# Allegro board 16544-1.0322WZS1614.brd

Outline 236 x 236 mm; copper layers: TOP, L2GND, L3, L4, L5GND, L6, L7GND, BOTTOM. Coordinates in mm from the lower left corner of the outline.
Outline path: 0,235 0,104 arc(0.29,103.29) 1,103 76.7,103 arc(77.41,102.71) 77.7,102 77.7,1 arc(77.99,0.29) 78.7,0 235,0 arc(235.71,0.29) 236,1 236,235 arc(235.71,235.71) 235,236 1,236 arc(0.29,235.71) 0,235 ; 8.75,233.25 9.25,233.25 arc(11.5,231) 9.25,228.75 8.75,228.75 arc(6.5,231) 8.75,233.25 ; 102.4,20.75 arc(103.15,20) 102.4,19.25 arc(101.65,20) 102.4,20.75 ; 109.1,65.95 arc(109.85,65.2) 109.1,64.45 arc(108.35,65.2) 109.1,65.95 ; 228.75,5.25 arc(231,7.5) 233.25,5.25 233.25,4.75 arc(231,2.5) 228.75,4.75 228.75,5.25

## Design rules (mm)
constraint set DEFAULT: min track width 0.127, pair gap 0.102
net group AUDIO_10: nets AUO_3V_POP1 AUO_3V_POP2
net group AUO_HDA_SDIN0_CPU_R: nets AUO_HDA_SDIN0_CPU_R HDA_SDIN0_CPU
net group CPU_USB20_HSD1-DIFF1: nets USB_CPU_PN1 USB_CPU_PP1
net group CPU_USB30_RX1-DIFF1: nets USB30_RX_CPU_N1 USB30_RX_CPU_P1
net group CPU_USB30_TX1-DIFF1: nets USB30_TX_CPU_N1 USB30_TX_CPU_P1
net group DDI0_VGA_DATA_CPU_N0: nets DDI0_VGA_DATA_CPU_N0 DDI0_VGA_DATA_CPU_N0_R
net group DDI0_VGA_DATA_CPU_N1: nets DDI0_VGA_DATA_CPU_N1 DDI0_VGA_DATA_CPU_N1_R
net group DDI0_VGA_DATA_CPU_N2: nets DDI0_VGA_DATA_CPU_N2 DDI0_VGA_DATA_CPU_N2_R
net group DDI0_VGA_DATA_CPU_N3: nets DDI0_VGA_DATA_CPU_N3 DDI0_VGA_DATA_CPU_N3_R
net group DDI0_VGA_DATA_CPU_P0: nets DDI0_VGA_DATA_CPU_P0 DDI0_VGA_DATA_CPU_P0_R
net group DDI0_VGA_DATA_CPU_P1: nets DDI0_VGA_DATA_CPU_P1 DDI0_VGA_DATA_CPU_P1_R
net group DDI0_VGA_DATA_CPU_P2: nets DDI0_VGA_DATA_CPU_P2 DDI0_VGA_DATA_CPU_P2_R
net group DDI0_VGA_DATA_CPU_P3: nets DDI0_VGA_DATA_CPU_P3 DDI0_VGA_DATA_CPU_P3_R
net group DDI1_DATA_CPU_N0: nets DDI1_DATA_CPU_N0 DDI1_DATA_CPU_N0_R
net group DDI1_DATA_CPU_N1: nets DDI1_DATA_CPU_N1 DDI1_DATA_CPU_N1_R
net group DDI1_DATA_CPU_N2: nets DDI1_DATA_CPU_N2 DDI1_DATA_CPU_N2_R
net group DDI1_DATA_CPU_N3: nets DDI1_DATA_CPU_N3 DDI1_DATA_CPU_N3_R
net group DDI1_DATA_CPU_P0: nets DDI1_DATA_CPU_P0 DDI1_DATA_CPU_P0_R
net group DDI1_DATA_CPU_P1: nets DDI1_DATA_CPU_P1 DDI1_DATA_CPU_P1_R
net group DDI1_DATA_CPU_P2: nets DDI1_DATA_CPU_P2 DDI1_DATA_CPU_P2_R
net group DDI1_DATA_CPU_P3: nets DDI1_DATA_CPU_P3 DDI1_DATA_CPU_P3_R
net group DIMM_ADD_CMD_CTL: nets DDR0_A_PARITY DDR1_B_PARITY
net group DMI_RX_CPU_N0: nets DMI_RX_CPU_N0 DMI_RX_CPU_N0_C
net group DMI_RX_CPU_N1: nets DMI_RX_CPU_N1 DMI_RX_CPU_N1_C
net group DMI_RX_CPU_N2: nets DMI_RX_CPU_N2 DMI_RX_CPU_N2_C
net group DMI_RX_CPU_N3: nets DMI_RX_CPU_N3 DMI_RX_CPU_N3_C
net group DMI_RX_CPU_P0: nets DMI_RX_CPU_P0 DMI_RX_CPU_P0_C
net group DMI_RX_CPU_P1: nets DMI_RX_CPU_P1 DMI_RX_CPU_P1_C
net group DMI_RX_CPU_P2: nets DMI_RX_CPU_P2 DMI_RX_CPU_P2_C
net group DMI_RX_CPU_P3: nets DMI_RX_CPU_P3 DMI_RX_CPU_P3_C
net group DMI_TX_CPU_N0: nets DMI_TX_CPU_N0 DMI_TX_CPU_N0_C
net group DMI_TX_CPU_N1: nets DMI_TX_CPU_N1 DMI_TX_CPU_N1_C
net group DMI_TX_CPU_N2: nets DMI_TX_CPU_N2 DMI_TX_CPU_N2_C
net group DMI_TX_CPU_N3: nets DMI_TX_CPU_N3 DMI_TX_CPU_N3_C
net group DMI_TX_CPU_P0: nets DMI_TX_CPU_P0 DMI_TX_CPU_P0_C
net group DMI_TX_CPU_P1: nets DMI_TX_CPU_P1 DMI_TX_CPU_P1_C
net group DMI_TX_CPU_P2: nets DMI_TX_CPU_P2 DMI_TX_CPU_P2_C
net group DMI_TX_CPU_P3: nets DMI_TX_CPU_P3 DMI_TX_CPU_P3_C
net group DP_HPD: nets DDI0_CRT_HPD DDI1_HDMI_HPD
net group GPP_CLK0N: nets GPP_CLK0N GPP_CLK0N_R
net group GPP_CLK0P: nets GPP_CLK0P GPP_CLK0P_R
net group GPU_EDP_AUX_SCL: nets GPU_EDP_AUX_SCL GPU_EDP_AUX_SCL_C
net group GPU_EDP_AUX_SDA: nets GPU_EDP_AUX_SDA GPU_EDP_AUX_SDA_C
net group GPU_EDP_IN0N: nets GPU_EDP_IN0N GPU_EDP_IN0N_C
net group GPU_EDP_IN0P: nets GPU_EDP_IN0P GPU_EDP_IN0P_C
net group GPU_EDP_IN1N: nets GPU_EDP_IN1N GPU_EDP_IN1N_C
net group GPU_EDP_IN1P: nets GPU_EDP_IN1P GPU_EDP_IN1P_C
net group GPU_EDP_IN2N: nets GPU_EDP_IN2N GPU_EDP_IN2N_C
net group GPU_EDP_IN2P: nets GPU_EDP_IN2P GPU_EDP_IN2P_C
net group GPU_EDP_IN3N: nets GPU_EDP_IN3N GPU_EDP_IN3N_C
net group GPU_EDP_IN3P: nets GPU_EDP_IN3P GPU_EDP_IN3P_C
net group GPU_HDMI_OUT0N: nets GPU_HDMI_OUT0N GPU_HDMI_OUT0N_C
net group GPU_HDMI_OUT0P: nets GPU_HDMI_OUT0P GPU_HDMI_OUT0P_C
net group GPU_HDMI_OUT1N: nets GPU_HDMI_OUT1N GPU_HDMI_OUT1N_C
net group GPU_HDMI_OUT1P: nets GPU_HDMI_OUT1P GPU_HDMI_OUT1P_C
net group GPU_HDMI_OUT2N: nets GPU_HDMI_OUT2N GPU_HDMI_OUT2N_C
net group GPU_HDMI_OUT2P: nets GPU_HDMI_OUT2P GPU_HDMI_OUT2P_C
net group GPU_HDMI_OUT_CKN: nets GPU_HDMI_OUT_CKN GPU_HDMI_OUT_CKN_C
net group GPU_HDMI_OUT_CKP: nets GPU_HDMI_OUT_CKP GPU_HDMI_OUT_CKP_C
net group HDA_SDOUT_CODEC: nets HDA_SDOUT_CODEC HDA_SDOUT_CPU
net group HDA_SYNC_CODEC: nets HDA_SYNC_CODEC HDA_SYNC_CPU
net group IPCC_CURRENT_SENSING: nets PWR_CHG_ACN PWR_CHG_ACP
net group PCH_GPP_RX0-DIFF1: nets PCIE_RX_PCH_N0 PCIE_RX_PCH_P0
net group PCH_USB20_HSD2-DIFF1: nets USB_PCH_PN2 USB_PCH_PP2
net group PCH_USB30_RX0-DIFF1: nets USB30_RX_PCH_N0 USB30_RX_PCH_P0
net group PCH_USB30_RX1-DIFF1: nets USB30_RX_PCH_N1 USB30_RX_PCH_P1
net group PCH_USB30_TX0-DIFF1: nets USB30_TX_PCH_N0 USB30_TX_PCH_P0
net group PCH_USB30_TX1-DIFF1: nets USB30_TX_PCH_N1 USB30_TX_PCH_P1
net group PCIE_SSD_RX5-DIFF1: nets PCIE_RX_SSDX4_N5 PCIE_RX_SSDX4_P5
net group PCIE_SSD_RX6-DIFF1: nets PCIE_RX_SSDX4_N6 PCIE_RX_SSDX4_P6
net group PCIE_SSD_RX7-DIFF1: nets PCIE_RX_SSDX4_N7 PCIE_RX_SSDX4_P7
net group PCIE_TX_CON_N0: nets PCIE_TX_CON_N0 PCIE_TX_PCH_N0
net group PCIE_TX_CON_P0: nets PCIE_TX_CON_P0 PCIE_TX_PCH_P0
net group PCIE_TX_LAN_N1: nets PCIE_TX_LAN_N1 PCIE_TX_PCH_N1
net group PCIE_TX_LAN_P1: nets PCIE_TX_LAN_P1 PCIE_TX_PCH_P1
net group PCIE_TX_SSDX4_N4: nets PCIE_TX_SSDX4_N4 PCIE_TX_SSDX4_N4_R
net group PCIE_TX_SSDX4_P4: nets PCIE_TX_SSDX4_P4 PCIE_TX_SSDX4_P4_R
net group PEG_CLK0_WLAN_N: nets PEG_CLK0_WLAN_N PEG_CLK0_WLAN_N_R
net group PEG_CLK0_WLAN_P: nets PEG_CLK0_WLAN_P PEG_CLK0_WLAN_P_R
net group PEG_CLK1_LAN_N: nets PEG_CLK1_LAN_N PEG_CLK1_LAN_N_R
net group PEG_CLK1_LAN_P: nets PEG_CLK1_LAN_P PEG_CLK1_LAN_P_R
net group PEG_CLK4_M2SSD_N: nets PEG_CLK4_M2SSD_N PEG_CLK4_M2SSD_N_R
net group PEG_CLK4_M2SSD_P: nets PEG_CLK4_M2SSD_P PEG_CLK4_M2SSD_P_R
net group PEG_CLK_CPU_N: nets PEG_CLK_CPU_N PEG_CLK_CPU_N_R
net group PEG_CLK_CPU_P: nets PEG_CLK_CPU_P PEG_CLK_CPU_P_R
net group PWR_40_10: nets PWR_0D775V_VIN PWR_12V_SVIN
net group PWR_PWM: nets PWR_VDDNBA_PWM PWR_VDDNBB_PWM
net group SATA_MUXSSD_TX-DIFF1: nets MUXSSD_TX_N1 MUXSSD_TX_P1
net group SATA_RX1-DIFF1: nets SATASSD_RX_DN1 SATASSD_RX_DP1
net group SATA_TX1-DIFF1: nets SATASSD_TX_DN1 SATASSD_TX_DP1
net group USB_CON_PN4: nets USB_CON_PN4 USB_PCH_PN4
net group USB_CON_PP4: nets USB_CON_PP4 USB_PCH_PP4
net group USB_PCH_DN3_NN: nets USB_PCH_DN3_NN USB_PCH_PN3
net group USB_PCH_DP3_PP: nets USB_PCH_DP3_PP USB_PCH_PP3
net group USB_PCH_PN13: nets USB_PCH_PN13 USB_TOUCH_N
net group USB_PCH_PP13: nets USB_PCH_PP13 USB_TOUCH_P
net group AMP_OUT: nets AMP_OUT_D_C WOOF_OUT_A_C1 WOOF_OUT_D_C1
net group AMP_SIGNAL: nets AMP_ASEL AMP_BST_A AMP_BST_B AMP_BST_C AMP_BST_C_C AMP_BST_D AMP_GVDD_AB AMP_GVDD_CD AMP_ISENSEP_L AMP_ISENSEP_R AMP_IVSENSE_L AMP_IVSENSE_R AMP_OC_ADJ AMP_PGVDD AMP_VREF1 AMP_VSENSEN_L AMP_VSENSEN_R GVDD_AB1 OC_ADJ1 PGVDD1 WOOF_ASEL_1 WOOF_BST_A1 WOOF_BST_B1 WOOF_BST_B_C1 WOOF_BST_C1 WOOF_BST_C_C1 WOOF_BST_D1 WOOF_GVDD_CD1 WOOF_ISENSEP_L1 WOOF_ISENSEP_R1 WOOF_IVSENSE_L1 WOOF_IVSENSE_R1 WOOF_VREF2 WOOF_VSENSEN_L1 WOOF_VSENSEN_R1
net group APU_DEBUG: nets APU_DBRDY APU_DBREQ# APU_TCK APU_TDI APU_TDO APU_TMS APU_TRST#
net group APU_FAN: nets CPU_FAN_CTRL_SIO CPU_FAN_TACH_SIO SYS_FAN_TACH1_1 SYS_FAN_TACH1_2 SYSTEM_FAN_PWM1_1
net group AUDIO_15: nets 1D8V_KBC 1D8V_SPI AUO_CBN1 AUO_CBN2 AUO_CBP1 AUO_CBP2 AUO_LDO1_CAP AUO_LDO2_CAP AUO_LDO3_CAP AUO_LINE1-VREF_O_L AUO_LINE1-VREF_O_L_N AUO_LINE1-VREF_O_L_R AUO_LINE1-VREF_O_R_N AUO_LINE1-VREF_O_R_R AUO_MIC1-VREF_O_L AUO_MIC1_CAP AUO_VREF1_1 AUO_VREF_1
net group AUDIO_20: nets AUO_IRQOUT
net group AUDIO_50: nets AUO_VD33STB
net group AUDIO_HPOUT: nets AUO_HPOUT_L AUO_HPOUT_R AUO_MIC1_L AUO_MIC1_R HPOL_CON HPOR_CON HPOUT_L_R HPOUT_R_R
net group AUDIO_I2C: nets AUO_POST_I2S_BCLK AUO_POST_I2S_BCLK_R AUO_POST_I2S_DIN AUO_POST_I2S_DIN_R AUO_POST_I2S_DOUT AUO_POST_I2S_DOUT_R AUO_POST_I2S_LRCK AUO_POST_I2S_LRCK_R
net group AUDIO_LINEOUT: nets AUO_LINE1_L AUO_LINE1_L_T AUO_LINE1_R AUO_LINE1_R_T AUO_LINEOUT_L AUO_LINEOUT_R
net group AUDIO_OTHERS: nets AUO_AGPO_1 AUO_AGPO_1_R AUO_BEEP_C AUO_BEEP_R AUO_CPVEE AUO_CPVPP AUO_EAPD AUO_HP_LINE1_JD AUO_HP_MUTE1 AUO_HP_MUTE2 AUO_HP_MUTE_R AUO_HPOUT_JD AUO_I2S_OUT_MIC1_JD AUO_INL_R2 AUO_INR_L1 AUO_INR_R1 AUO_INR_R2 AUO_LINEOUT_JD AUO_MONITOR_SW AUO_SET1 AUO_SET2 AUO_SIO_HP_MUTE AUO_SPDIF_IN AUO_SPDIF_IN_R PC_MONITOR_SW_D PC_MONITOR_SW_G PDB
net group AUO_LINK_BCLK: nets AUO_LINK_BCLK HDA_BITCLK_CODEC HDA_BITCLK_CPU
net group AUO_RESET_OUT: nets AUO_RESET_OUT HDA_RST#_CODEC HDA_RST#_CPU
net group CHAR_CONTROL: nets CHAR_CTL1_REAR CHAR_CTL1_SIDE CHAR_CTL2_REAR CHAR_CTL2_SIDE CHAR_CTL3_REAR CHAR_CTL3_SIDE PCH_CHAR_CTL3_REAR PCH_CHAR_CTL3_SIDE
net group CHAR_ENABLE: nets CHAR_EN_REAR CHAR_EN_REAR_EC CHAR_EN_SIDE CHAR_EN_SIDE_EC
net group CHAR_OTHERS: nets CHAR_ILIM_HI_REAR CHAR_ILIM_HI_SIDE CHAR_ILIM_LO_REAR CHAR_ILIM_LO_SIDE CHAR_ILIM_SEL_REAR CHAR_ILIM_SEL_SIDE
net group CLK_100M: nets CLK_100M CLK_100M_R XIN_OSC
net group CLKREQ: nets CLK_REQG_L NGFF_CLKREQ1_N PEG_CLKREQ0_NGFF#_C PEG_CLKREQ0_WLAN# PEG_CLKREQ0_WLAN_C PEG_CLKREQ1_LAN# PEG_CLKREQ4_SSD# PEG_CLKREQ5# PEX_CLKREQ_R
net group CPU_VSENSE: nets CPU_CORE_FB_N CPU_CORE_FB_N_R CPU_CORE_FB_P CPU_CORE_FB_P_R CPU_NB_FB_P CPU_NB_FB_P_R
net group DDR_SEQUENCE: nets SE_BJT_B1 SE_BJT_B2 SE_BJT_B3 SE_VDDQ_EN SE_VPP_EN_B
net group DIMM_MISC_A: nets M_A_EVENT# SM_A_DRAMRST# SM_A_DRAMRST#_R
net group DIMM_MISC_B: nets DDR1_B_ALERT_N M_B_EVENT# SM_B_DRAMRST# SM_B_DRAMRST#_R
net group DIMM_SA_SIGNAL: nets SA0_DIMM1 SA0_DIMM2 SA1_DIMM1 SA1_DIMM2 SA2_DIMM1 SA2_DIMM2
net group EC_GPIO: nets AC_OK# EC_BEEP_GPIO_EC EC_CLEAR_RTC EC_PECI EC_SCI# EC_SMI# EC_SWI# ECSCI#_KBC ECSMI#_KBC ECSWI#_KBC GPU_DPLUS KBC_ON#_GATE KBC_ON#_GATE_L KBC_VCORF PSL_IN1# PSL_IN2# PSL_OUT# SDCARD_DET_EC SIO_GREEN_PWM SIO_PME_N SIO_YELLOW SW_ON_N_SIO VD1_EN# VD_IN1 VD_IN2 VD_OUT1# VD_OUT2#
net group EC_SPI_CLK: nets EC_SPI_CLK KBC_SPI_CLK SPI_CLK_CPU
net group EC_SPI_CS0_N: nets EC_SPI_CS0_N KBC_SPI_CS0_N SPI_CS0_N_CPU
net group EC_SPI_SI: nets EC_SPI_SI KBC_SPI_MOSI SPI_SO_CPU_R
net group EC_SPI_SO: nets EC_SPI_SO KBC_SPI_MISO SPI_MISO_CPU
net group GPIO: nets ADAPTOR_PSID ADAPTOR_PSID_R AGPIO89 AUO_DMIC_DET BIST_EN_INV CLEAN_CMOS_EC CMOS_EC_R CORETYPE0 CORETYPE1 CYPD2122_WP DPLVDS_PWMIN DPLVDS_PWMIN_CPU EC_SENSE_BT1 EDP_CABLE_DET EGPIO97 FDT_OVRD_GPIO FDT_OVRD_GPIO_C GPU_BLON_PWM GPU_GPIO_8_ROMSO_R GPU_GPIO_9_ROMSI_R GPU_GPIO_10_ROMSCK GPU_GPIO_10_ROMSCK_R GPU_GPIO_11 GPU_GPIO_12 GPU_GPIO_13 GPU_GPIO_15 GPU_GPIO_19_CTF GPU_GPIO_19_CTF_R GPU_GPIO_20 GPU_GPIO_22_ROMCSB GPU_GPIO_22_ROMCSB_R GPU_GPIO_29 GPU_GPIO_30_PCC_R HDMI_DET HOOD_SW_DET# INT#_TYPEC INT_SERIRQ IPCC_CPU0 IPCC_CPU0_R IPCC_CPU1 IPCC_CPU1_R IPCC_CPU2 IPCC_CPU2_R JACK_PSID LAN_DISABLE_N LPC_PME_N_R LPC_SMI_L M2_PEDET ME_CNTL1 ME_UNLOCK MODEL_ID_DET NC7SB3157_S NGFF_PEWAKE0_N OSD_CONTROL_SEL OSD_MENU OSD_MENU_EC OSD_MENU_R PANEL_ON PB_IN_SW1 PCB_VER_ID PCH_SUSCLK_WLAN PCIE_WAKE# PM_DEBUG_ENABLE PM_GPIO0_X16_PRSNT PM_GPIO1_PCIEX16_DET0 PM_GPIO2_PCIEX16_DET1 PM_GPIO3_PCIEX16_DET2 PM_GPIO4_SSD_DET PM_GPIO_R0 PM_GPIO_R1 PM_GPIO_R2 PM_GPIO_R3 PM_GPIO_R4 PM_GPIO_R5 PM_GPIO_R6 PM_GPIO_R7 PM_GPIO_R8 PM_GPIO_R9 PM_GPIO_R11 PM_GPIO_R12 PM_GPP_INT_PCI_WAKE PM_IFDET0 PM_IFDET1 PM_INT PM_PCIE_WAKE# PM_PKG0 PM_PKG1 PM_PWRBTN_N PM_TESTEN PM_UART_TX PSID_D PSID_D_1 PSID_G PSW_GPIO PWRBTN_N PWRBTN_N_R PWRCN_DET_EC RDISPLAY1_DET_EC RDISPLAY2_DET_EC RLAN_AUDIO_DET_EC RPWR_CN1_DET_EC RTC_DET# RTYPEC_DET_EC RUSB3_DET_EC S5_MUX_APU SMBUS_ISP SPKR SPKR_DET SPKR_DET_C SUSB_DET_EC SUSCLK SUSCLK_NGFF SW_CMOS TOUCH_DET TP_DBGDATA_3_R TP_DBGDATA_4_R TP_DBGDATA_5_R TYPEC_STATUS WEBCAM_DET WOOF_DET_C
net group GPU_ADBIA0_D1: nets ADBIA0 ADBIA1 ADBIB0 ADBIB1 ADBIC0 ADBIC1 ADBID0 ADBID1
net group GPU_CKEA0_D1: nets CKEA0 CKEA1 CKEB0 CKEB1 CKEC0 CKEC1 CKED0 CKED1
net group GPU_CSA0B_CSD1B: nets CSA0B_0 CSA1B_0 CSB0B_0 CSB1B_0 CSC0B_0 CSC1B_0 CSD0B_0 CSD1B_0
net group GPU_DDBIA0: nets DDBIA0_0 DDBIA0_1 DDBIA0_2 DDBIA0_3
net group GPU_DDBIA1: nets DDBIA1_0 DDBIA1_1 DDBIA1_2 DDBIA1_3
net group GPU_DDBIB0: nets DDBIB0_0 DDBIB0_1 DDBIB0_2 DDBIB0_3
net group GPU_DDBIB1: nets DDBIB1_0 DDBIB1_1 DDBIB1_2 DDBIB1_3
net group GPU_DDBIC0: nets DDBIC0_0 DDBIC0_1 DDBIC0_2 DDBIC0_3
net group GPU_DDBIC1: nets DDBIC1_0 DDBIC1_1 DDBIC1_2 DDBIC1_3
net group GPU_DDBID0: nets DDBID0_0 DDBID0_1 DDBID0_2 DDBID0_3
net group GPU_DDBID1: nets DDBID1_0 DDBID1_1 DDBID1_2 DDBID1_3
net group GPU_DQA0_0_31: nets DQA0_0 DQA0_1 DQA0_2 DQA0_3 DQA0_4 DQA0_5 DQA0_6 DQA0_7 DQA0_8 DQA0_9 DQA0_10 DQA0_11 DQA0_12 DQA0_13 DQA0_14 DQA0_15 DQA0_16 DQA0_17 DQA0_18 DQA0_19 DQA0_20 DQA0_21 DQA0_22 DQA0_23 DQA0_24 DQA0_25 DQA0_26 DQA0_27 DQA0_28 DQA0_29 DQA0_30 DQA0_31
net group GPU_DQA1_0_31: nets DQA1_0 DQA1_1 DQA1_2 DQA1_3 DQA1_4 DQA1_5 DQA1_6 DQA1_7 DQA1_8 DQA1_9 DQA1_10 DQA1_11 DQA1_12 DQA1_13 DQA1_14 DQA1_15 DQA1_16 DQA1_17 DQA1_18 DQA1_19 DQA1_20 DQA1_21 DQA1_22 DQA1_23 DQA1_24 DQA1_25 DQA1_26 DQA1_27 DQA1_28 DQA1_29 DQA1_30 DQA1_31
net group GPU_DQB0_0_31: nets DQB0_0 DQB0_1 DQB0_2 DQB0_3 DQB0_4 DQB0_5 DQB0_6 DQB0_7 DQB0_8 DQB0_9 DQB0_10 DQB0_11 DQB0_12 DQB0_13 DQB0_14 DQB0_15 DQB0_16 DQB0_17 DQB0_18 DQB0_19 DQB0_20 DQB0_21 DQB0_22 DQB0_23 DQB0_24 DQB0_25 DQB0_26 DQB0_27 DQB0_28 DQB0_29 DQB0_30 DQB0_31
net group GPU_DQB1_0_31: nets DQB1_0 DQB1_1 DQB1_2 DQB1_3 DQB1_4 DQB1_5 DQB1_6 DQB1_7 DQB1_8 DQB1_9 DQB1_10 DQB1_11 DQB1_12 DQB1_13 DQB1_14 DQB1_15 DQB1_16 DQB1_17 DQB1_18 DQB1_19 DQB1_20 DQB1_21 DQB1_22 DQB1_23 DQB1_24 DQB1_25 DQB1_26 DQB1_27 DQB1_28 DQB1_29 DQB1_30 DQB1_31
net group GPU_DQC0_0_31: nets DQC0_0 DQC0_1 DQC0_2 DQC0_3 DQC0_4 DQC0_5 DQC0_6 DQC0_7 DQC0_8 DQC0_9 DQC0_10 DQC0_11 DQC0_12 DQC0_13 DQC0_14 DQC0_15 DQC0_16 DQC0_17 DQC0_18 DQC0_19 DQC0_20 DQC0_21 DQC0_22 DQC0_23 DQC0_24 DQC0_25 DQC0_26 DQC0_27 DQC0_28 DQC0_29 DQC0_30 DQC0_31
net group GPU_DQC1_0_31: nets DQC1_0 DQC1_1 DQC1_2 DQC1_3 DQC1_4 DQC1_5 DQC1_6 DQC1_7 DQC1_8 DQC1_9 DQC1_10 DQC1_11 DQC1_12 DQC1_13 DQC1_14 DQC1_15 DQC1_16 DQC1_17 DQC1_18 DQC1_19 DQC1_20 DQC1_21 DQC1_22 DQC1_23 DQC1_24 DQC1_25 DQC1_26 DQC1_27 DQC1_28 DQC1_29 DQC1_30 DQC1_31
net group GPU_DQD0_0_31: nets DQD0_0 DQD0_1 DQD0_2 DQD0_3 DQD0_4 DQD0_5 DQD0_6 DQD0_7 DQD0_8 DQD0_9 DQD0_10 DQD0_11 DQD0_12 DQD0_13 DQD0_14 DQD0_15 DQD0_16 DQD0_17 DQD0_18 DQD0_19 DQD0_20 DQD0_21 DQD0_22 DQD0_23 DQD0_24 DQD0_25 DQD0_26 DQD0_27 DQD0_28 DQD0_29 DQD0_30 DQD0_31
net group GPU_DQD1_0_31: nets DQD1_0 DQD1_1 DQD1_2 DQD1_3 DQD1_4 DQD1_5 DQD1_6 DQD1_7 DQD1_8 DQD1_9 DQD1_10 DQD1_11 DQD1_12 DQD1_13 DQD1_14 DQD1_15 DQD1_16 DQD1_17 DQD1_18 DQD1_19 DQD1_20 DQD1_21 DQD1_22 DQD1_23 DQD1_24 DQD1_25 DQD1_26 DQD1_27 DQD1_28 DQD1_29 DQD1_30 DQD1_31
net group GPU_EDCA0_0_3: nets EDCA0_0 EDCA0_1 EDCA0_2 EDCA0_3
net group GPU_EDCA1_0_3: nets EDCA1_0 EDCA1_1 EDCA1_2 EDCA1_3
net group GPU_EDCB0_0_3: nets EDCB0_0 EDCB0_1 EDCB0_2 EDCB0_3
net group GPU_EDCB1_0_3: nets EDCB1_0 EDCB1_1 EDCB1_2 EDCB1_3
net group GPU_EDCC0_0_3: nets EDCC0_0 EDCC0_1 EDCC0_2 EDCC0_3
net group GPU_EDCC1_0_3: nets EDCC1_0 EDCC1_1 EDCC1_2 EDCC1_3
net group GPU_EDCD0_0_3: nets EDCD0_0 EDCD0_1 EDCD0_2 EDCD0_3
net group GPU_EDCD1_0_3: nets EDCD1_0 EDCD1_1 EDCD1_2 EDCD1_3
net group GPU_MAA0_1_8: nets MAA0_0 MAA0_1 MAA0_2 MAA0_3 MAA0_4 MAA0_5 MAA0_6 MAA0_7 MAA0_8
net group GPU_MAA1_1_8: nets MAA1_0 MAA1_1 MAA1_2 MAA1_3 MAA1_4 MAA1_5 MAA1_6 MAA1_7 MAA1_8
net group GPU_MAB0_1_8: nets MAB0_0 MAB0_1 MAB0_2 MAB0_3 MAB0_4 MAB0_5 MAB0_6 MAB0_7 MAB0_8
net group GPU_MAB1_1_8: nets MAB1_0 MAB1_1 MAB1_2 MAB1_3 MAB1_4 MAB1_5 MAB1_6 MAB1_7 MAB1_8
net group GPU_MAC0_1_8: nets MAC0_0 MAC0_1 MAC0_2 MAC0_3 MAC0_4 MAC0_5 MAC0_6 MAC0_7 MAC0_8
net group GPU_MAC1_1_8: nets MAC1_0 MAC1_1 MAC1_2 MAC1_3 MAC1_4 MAC1_5 MAC1_6 MAC1_7 MAC1_8
net group GPU_MAD0_1_8: nets MAD0_0 MAD0_1 MAD0_2 MAD0_3 MAD0_4 MAD0_5 MAD0_6 MAD0_7 MAD0_8
net group GPU_MAD1_1_8: nets MAD1_0 MAD1_1 MAD1_2 MAD1_3 MAD1_4 MAD1_5 MAD1_6 MAD1_7 MAD1_8
net group GPU_MEM_CALR: nets MEM_CALRA MEM_CALRB MEM_CALRC MEM_CALRD
net group GPU_OTHERS: nets CTF_TRIP FB_VDDC_VR FB_VDDCI FB_VSSC GPU_AUX_ZVSS GPU_EDP_HPD GPU_EDP_HPD3 GPU_EDP_HPD4 GPU_GPIO_1 GPU_GPIO_8_ROMSO GPU_GPIO_9_ROMSI GPU_HPD_HDMI GPU_P_ZVSS GPU_PPC_EC GPU_PPC_R GPU_VCC3_CTL GPU_VCC3_CTL_2 GPU_WAKEB HSYNC MF_A0 MF_A1 MF_B0 MF_B1 MF_C0 MF_C1 MF_D0 MF_D1 MVREF_A MVREF_B MVREF_C MVREF_D P2800_DXN P2800_DXP SEN_A0 SEN_A1 SEN_B0 SEN_B1 SEN_C0 SEN_C1 SEN_D0 SEN_D1 SSON# TSS_TEST6 U2506_CLKOUT U2506_INT# VREFC_A0 VREFC_A1 VREFC_B0 VREFC_B1 VREFC_C0 VREFC_C1 VREFC_D0 VREFC_D1 VREFD1_A0 VREFD1_A1 VREFD1_B0 VREFD1_B1 VREFD1_C0 VREFD1_C1 VREFD1_D0 VREFD1_D1 VREFD2_A0 VREFD2_A1 VREFD2_B0 VREFD2_B1 VREFD2_C0 VREFD2_C1 VREFD2_D0 VREFD2_D1 VSYNC ZQ_A0 ZQ_A1 ZQ_B0 ZQ_B1 ZQ_C0 ZQ_C1 ZQ_D0 ZQ_D1
net group GPU_RAS_CAS_WEA_CSA_CKE_A1: nets CASA1B RASA1B WEA1B
net group GPU_RAS_CAS_WEA_CSA_CKEA_A0: nets CASA0B RASA0B WEA0B
net group GPU_RAS_CAS_WEB_CSB_CKE_B0: nets CASB0B RASB0B WEB0B
net group GPU_RAS_CAS_WEB_CSB_CKE_B1: nets CASB1B RASB1B WEB1B
net group GPU_RAS_CAS_WEC_CSC_CKE_C0: nets CASC0B RASC0B WEC0B
net group GPU_RAS_CAS_WEC_CSC_CKE_C1: nets CASC1B RASC1B WEC1B
net group GPU_RAS_CAS_WED_CSD_CKE_D0: nets CASD0B RASD0B WED0B
net group GPU_RAS_CAS_WED_CSD_CKE_D1: nets CASD1B RASD1B WED1B
net group HDT: nets HDT1_11 HDT1_13 HDT1_15 HDT_DBREQ# HDT_TRST#
net group IPCC_OTHERS: nets IPCC_AC_PROTECT IPCC_INT_SIO# IPCC_V_SENSE IPCC_XRES# IPPC_GPU_CMP IPPC_GPU_CMP_R IPPC_GPU_MAN IPPC_GPU_PPC
net group JTAG: nets JTAG_BP_0 JTAG_BP_0_R JTAG_BP_1 JTAG_BP_1_R JTAG_DRAIN JTAG_GATE JTAG_TCK JTAG_TDI JTAG_TDO JTAG_TMS JTAG_TRSTB TESTEN
net group LPC: nets L_AD0 L_AD1 L_AD2 L_AD3 L_FRAME_N
net group MUXSSD_RX_N0: nets MUXSSD_RX_N0_R
net group MUXSSD_RX_P0: nets MUXSSD_RX_P0_R
net group NGFF_OTHERS: nets MPCIE_DISABLE_N NGFF_BT_DISABLE NGFF_PEWAKE1_N NGFF_W_DISABLE1_N NGFF_W_DISABLE2_N
net group PLTRST: nets DRAM_RST1 DRAM_RST1_R DRAM_RST1_RR DRAM_RST2 DRAM_RST2_R DRAM_RST2_RR EC_AUD_RST_N EC_AVCC ECRST# ESPI_RESET_L/KBRST_L PCIE_RST# PCIE_RST#_APU PCIE_RST#_APU_R PLT_RST#_APU PLT_RST#_R PLTRST#_EC_R PLTRST_LAN_N PLTRST_N_1 PLTRST_SSD PM_PCIE_RST RSMRST#_CPU RSMRST_H RSMRST_SIO_N RSMRST_SIO_R RST#_CPU SYS_RESET_L
net group PWR_10_10: nets PWR_0D8V_EN PWR_0D8V_ILMT PWR_0D8V_PG PWR_0D9V_PG PWR_0D775V_EN PWR_0D775V_EN_R PWR_0D775V_VREF PWR_1D05V_EN PWR_1D5V_EN PWR_1D05V_ILMT PWR_1D05V_PG PWR_1D5V_PG PWR_1D8V_EN PWR_1D8V_ILMT PWR_1D8V_PG PWR_1D8V_VCC PWR_1D8V_VGA_EN PWR_1D8V_VGA_PG PWR_1D35V_CS PWR_1D35V_EN PWR_1D35V_PG PWR_1D35V_TON PWR_1D35V_VTTREF PWR_2D5V_EN PWR_2D5V_PCH_EN PWR_2D5V_PCH_PG PWR_2D5V_PG PWR_3D3V_5V_PG PWR_3D3V_CS2 PWR_3D3V_EN2 PWR_3D3V_LDO3 PWR_5V_CS1 PWR_5V_EN1 PWR_5V_LDO5 PWR_12V_EN PWR_12V_PG PWR_12V_SS PWR_12V_VCC PWR_VCCDDC_SENSE_A PWR_VCCDDC_SENSE_B PWR_VCCDDCI_SENSE_A PWR_VCCDDCI_SENSE_B PWR_VCORE_COMP PWR_VCORE_EN PWR_VCORE_IMON PWR_VCORE_ISEN1 PWR_VCORE_ISEN2 PWR_VCORE_ISEN3 PWR_VCORE_ISUMN PWR_VCORE_ISUMN_A PWR_VCORE_PG PWR_VCORE_RTN PWR_VCORE_SVC PWR_VCORE_SVD PWR_VCORE_SVT PWR_VCORE_VRHOT PWR_VCORE_VSEB PWR_VCORE_VSUM_P PWR_VDDC_ADDRESS PWR_VDDC_CONFIG PWR_VDDC_EN PWR_VDDC_PALERT# PWR_VDDC_PCLK PWR_VDDC_PDATA PWR_VDDC_PG PWR_VDDC_PG_A PWR_VDDC_SALERT# PWR_VDDC_SCLK PWR_VDDC_SDATA PWR_VDDC_TEMP PWR_VDDC_THWN PWR_VDDC_VCCS PWR_VDDC_VDDIO PWR_VDDC_VRHOT PWR_VDDCA_EN_A PWR_VDDCA_ISEN_P_A PWR_VDDCA_SMOD# PWR_VDDCA_THWN# PWR_VDDCB_EN_A PWR_VDDCB_ISEN_P_A PWR_VDDCB_SMOD# PWR_VDDCB_THWN# PWR_VDDCC_EN_A PWR_VDDCC_ISEN_P_A PWR_VDDCC_SMOD# PWR_VDDCC_THWN# PWR_VDDCD_EN_A PWR_VDDCD_ISEN_N_A PWR_VDDCD_ISEN_P_A PWR_VDDCD_SMOD# PWR_VDDCD_THWN# PWR_VDDCE_EN_A PWR_VDDCE_ISEN_N_A PWR_VDDCE_ISEN_P_A PWR_VDDCE_SMOD# PWR_VDDCE_THWN# PWR_VDDCF_EN_A PWR_VDDCF_ISEN_N_A PWR_VDDCF_ISEN_P_A PWR_VDDCF_SMOD# PWR_VDDCF_THWN# PWR_VDDCI_EN PWR_VDDCI_EN_A PWR_VDDCI_ISEN_P_A PWR_VDDCI_PG PWR_VDDCI_PG_A PWR_VDDCI_SMOD# PWR_VDDCI_TEMP PWR_VDDCI_THWN PWR_VDDCI_THWN# PWR_VDDNB_COMP PWR_VDDNB_FCCM PWR_VDDNB_IMON PWR_VDDNB_ISEN1 PWR_VDDNB_ISEN2 PWR_VDDNB_ISUMN PWR_VDDNB_ISUMN_A PWR_VDDNB_VSEN PWR_VDDNB_VSUMP PWR_VDDP_EN PWR_VDDP_PFM PWR_VDDP_PG PWR_VDDP_SS PWR_VDDP_TON PWR_VDDQ_CS PWR_VDDQ_EN PWR_VDDQ_EN_R PWR_VDDQ_PG PWR_VDDQ_TON PWR_VDDQ_VTTREF PWR_VGA_PG PWR_VR_PG PWR_VSSDDC_SENSE_A PWR_VSSDDCI_SENSE_A PWR_VTT_EN PWR_VTT_EN_R
net group PWR_20_10: nets PWR_1D05V_VCC PWR_1D35V_VDD PWR_1D35V_VID PWR_VCORE_VDDIO PWR_VDDC_VCC PWR_VDDC_VINSEN PWR_VDDQ_VDD PWR_VDDQ_VID
net group PWR_20_20: nets PWR_0D8V_BOOT PWR_0D8V_BOOT_A PWR_0D8V_FB PWR_0D9V_FB PWR_1D05V_BOOT PWR_1D05V_BOOT_A PWR_1D05V_FB PWR_1D5V_FB PWR_1D05V_FB_A PWR_1D8V_BOOT PWR_1D8V_BOOT_A PWR_1D8V_FB PWR_1D8V_FB_A PWR_1D8V_VGA_FB PWR_1D35V_BOOT PWR_1D35V_BOOT_A PWR_1D35V_FB PWR_1D35V_SNUB PWR_2D5V_FB PWR_3D3V_BOOT2 PWR_3D3V_BOOT2_A PWR_3D3V_FB2 PWR_3D3V_FB2_A PWR_3D3V_SNUB PWR_5V_BOOT1 PWR_5V_BOOT1_A PWR_5V_BYP1 PWR_5V_FB1 PWR_5V_FB1_A PWR_5V_SNUB PWR_12V_BOOT_A PWR_12V_FB_A PWR_12V_SNB PWR_VCORE_FB PWR_VCORE_FB2 PWR_VCORE_FB_A PWR_VCORE_FB_B PWR_VCORE_FB_C PWR_VCOREA_BOOT PWR_VCOREA_BOOT_A PWR_VCOREA_SNB PWR_VCOREB_BOOT_A PWR_VCOREB_SNB PWR_VCOREC_BOOT_A PWR_VCOREC_SNB PWR_VDDCA_BOOT PWR_VDDCA_BOOT_A PWR_VDDCA_SNB PWR_VDDCB_BOOT PWR_VDDCB_BOOT_A PWR_VDDCB_SNB PWR_VDDCC_BOOT PWR_VDDCC_BOOT_A PWR_VDDCC_SNB PWR_VDDCD_BOOT PWR_VDDCD_BOOT_A PWR_VDDCD_SNB PWR_VDDCE_BOOT PWR_VDDCE_BOOT_A PWR_VDDCE_SNB PWR_VDDCF_BOOT PWR_VDDCF_BOOT_A PWR_VDDCF_SNB PWR_VDDCI_BOOT PWR_VDDCI_BOOT_A PWR_VDDCI_SNB PWR_VDDNB_FB PWR_VDDNB_FB_A PWR_VDDNB_FB_B PWR_VDDNB_FB_C PWR_VDDNBA_BOOT PWR_VDDNBA_BOOT_A PWR_VDDNBA_VCC PWR_VDDNBB_BOOT PWR_VDDNBB_BOOT_A PWR_VDDNBB_SNB PWR_VDDP_BT PWR_VDDP_FB PWR_VDDP_FB_A PWR_VDDP_FB_B PWR_VDDP_FB_C PWR_VDDQ_BOOT PWR_VDDQ_BOOT_A PWR_VDDQ_FB PWR_VDDQ_SNUB VDDNB_SN1
net group PWR_60_10: nets GPU_VBIOS_PWR PWR_1D35V_VDDQ PWR_VDDQ_VDDQ
net group PWR_EE_10: nets 1D05V_PCH_S0_CT1 5V_S0_CT1 AD+_2 AMP_LDO_1D5 EC_AD0 EC_VSBY IPCC_CMP_VREF IPCC_VCCD IPCC_VREF WOOF_LDO_1D5_1
net group PWR_EE_20: nets 1D5V_DVDD_IO_S5 1D8V_S0_CT2 3D3V_DVDD_MIC 3D3V_MUX_S0 3D3V_PCH_S0 3D3V_S0_CT2 5V_CODEC_DIGITAL_S0 +TSVDD CLK_100M_VDD EFUSE_PWR VDDIO_AUDIO
net group PWR_EE_30: nets EC_VBKUP V_3P0_BAT_VREG VBAT1 VBAT1_R
net group PWR_EE_40: nets 3D3V_AUX_S5 3D3V_VDD_S0 EC_3D3V_S0 EC_VCC1D8V_S5 EC_VDD3D3 G2042_VDDCR_C IPCC_3D3V_S5 KBC_VCC
net group PWR_EE_100: nets EC_AGND
net group PWR_GATE_SNUBBER_BOOT_PHASE: nets PWR_1D35V_HG PWR_1D35V_LG PWR_3D3V_HG2 PWR_3D3V_LG2 PWR_VDDNBA_HG PWR_VDDNBB_LG PWR_VDDQ_HG
net group PWR_GPU_PWM: nets PWR_VDDCA_PWM PWR_VDDCA_PWM_A PWR_VDDCB_PWM PWR_VDDCB_PWM_A PWR_VDDCC_PWM PWR_VDDCC_PWM_A PWR_VDDCD_PWM PWR_VDDCD_PWM_A PWR_VDDCE_PWM PWR_VDDCE_PWM_A PWR_VDDCF_PWM PWR_VDDCF_PWM_A PWR_VDDCI_PWM PWR_VDDCI_PWM_A
net group PWRGD_EN: nets 0D8V_PG 1D05V_PCH_S0_EN 1D05V_PCH_S5_PG 1D05V_PCH_S5_PG_EC 1D05V_S0_EN 1D5V_S5_PG 1D05V_S5_PWRGD 1D8V_S0_EN 1D8V_S5_PG 1D8V_SPI_EN 1D8V_SPI_EN2 1D8V_SPI_EN3 1D8V_VGA_PG 2D5V_EN 2D5V_PCH_S0_PG 2D5V_S5_PG 3V_5V_POK 5V_3D3V_S0_EN 12V_PG ALERT#_CPU ALL_PWRGD_2 ALL_SYS_PWRGD ALL_SYS_PWRGD_C ALL_SYS_PWRGD_EC GPIO_6_TACH GPU_TEST_PG GPU_TEST_PG_B GPU_TEST_PG_BACO GPU_TEST_PG_BACO_B H_PROCHOT_N H_PROCHOT_N_EC HDT_PWR_EN1 HDT_PWR_EN2 HDT_PWR_EN3 MAINPOWER_CONTROL NC7SB3157_A NPMALERT NSVALERT NVRHOT PGOOD_NB PM_PWGD PURE_HW_SHUTDOWN# PURE_HW_SHUTDOWN#_R PWR_5V3V_EMN_R PWRGD_3V_N PX_EN PX_EN_G PX_ENB S5_ENABLE SE_VPP_EN SIO_EUP_EN# SUS_CLK_CPU_EN SVID_PWRGD T_CRIT# THERM_SYS_SHDN# THERMTRIP_L_CPU THERMTRIP_L_CPU_EC USB_EN_S3WAKE USBVCC31_EN USBVCC32_EN USBVCCTP_EN USBVCCTP_EN_R VCORE_MEM_TEST_PG VCORE_MEM_TEST_PG_BACO VDDP_S5_PG VDDP_S5_PG_EC
net group SATAHDR_RX_DN0: nets SATA__RXN0_C SATA_RXN0_C_N SATAHDR_RX_DN0
net group SATAHDR_RX_DP0: nets SATA__RXP0_C SATA_RXP0_C_N SATAHDR_RX_DP0
net group SATAHDR_TX_DN0: nets SATA__TXN0_C SATA_TXN0_C_N SATAHDR_TX_DN0
net group SATAHDR_TX_DP0: nets SATA__TXP0_C SATA_TXP0_C_N SATAHDR_TX_DP0
net group SINGAL_PD: nets DP_AUX_ZVSS DP_ZVSS FWH_ID0 GPU_DP_ZVSS MA_ZVSS MB_ZVSS P_ZVSS PM_UREXT PREXT STRAP_LPC_CLK_CPU_P0 TEST0_APU TEST1_APU TEST2_APU TEST18_APU TEST19_APU
net group SINGAL_PH: nets AGPIO5_DEVSLP0 ALERT# AM4R1 CLK_REQ0 CLK_REQ1 CLK_REQ2 DP_STEREOSYNC_APU GPU_DP_ZVDD_08 INIT_3V MA_ZV MB_ZV NC7SB3157_B0 NC7SB3157_B1 P_ZVDDP SATA_ZVDDP SIO_SMCLK0 SIO_SMDAT0 STRAP_LPC_CLK_CPU_P1 USB_GPIO_C12 USB_GPIO_C13 VDDQ_BLEED_R1 VDDQ_BLEED_R2
net group SINGLE_ENDED_CLOCK: nets CLK_100M_XIN CLK_100M_XOUT LPC_CLK0 LPC_CLK1 LPC_CLK_D PM_XTAL_25M_IN PM_XTAL_25M_IN_R PM_XTAL_25M_OUT PM_XTAL_25M_OUT_R PROCHOT#_CPU_Q SUS_CLK_CPU_PWR X32K_RTC XTL_32K_XI_RTC XTL_32K_XO_RTC
net group SLP_S3_S5: nets SLP_S3_N_EC SLP_S5_N SLP_S5_N_EC
net group SMBUS: nets AMDTSI_CLK_CPU AMDTSI_DATA_CPU AMP_I2C_SCL AMP_I2C_SDA AUO_DMIC_CLK1 AUO_DMIC_CLK1_R AUO_DMIC_CLK2 AUO_DMIC_CLK2_R AUO_DMIC_DATA1 AUO_DMIC_DATA1_R AUO_DMIC_DATA2 AUO_DMIC_DATA2_R DDCVGACLK DDCVGADAT EC_I2C_CLK EC_I2C_DATA GPU_I2C_SCL GPU_I2C_SDA GPU_SMB_CLK_MAIN GPU_SMB_CLK_MAIN_G GPU_SMB_DATA_MAIN GPU_SMB_DATA_MAIN_G I2C3_CLK_RESUME I2C3_DATA_RESUME I2C_CLK I2C_CLK_CN I2C_DATA I2C_DATA_CN IPCC_I2C_CLK IPCC_I2C_CLK_R IPCC_I2C_DATA IPCC_I2C_DATA_R IPCC_SWD_CLK IPCC_SWD_DATA NCT_CLK NCT_DATA PMSCL PMSDA SMB_CLK_MAIN SMB_DATA_MAIN SML1_CLK_SIO SML1_DATA_SIO SVCLK SVDATA SVID_CLK SVID_DATA TYPE_C_CLK TYPE_C_DATA WOOF_I2C_SCL1 WOOF_I2C_SDA1
net group SPI: nets KBC_SPI_IO2 KBC_SPI_IO3 PM_SPI_SCK PM_SPI_SDI PM_SPI_SDO SPI_CS2_CPU
net group SPI_IO2: nets SPI_IO2_CPU
net group SPI_IO3: nets SPI_IO3_CPU
net group SSD_OTHERS: nets DEVSLP DEVSLP_N DEVSLP_N_GATE MUXSSD_OE# MUXSSD_SEL MUXSSD_SEL_EN MUXSSD_SEL_EN_C PEDET_B SSD_DEVSLP_N SSD_PM_PCIE_WAKE# TP_BBR#
net group TP: nets EC_DEBUG PM_TCK PM_TDI PM_TDO PM_TMS PM_UART_RX PPON_0 PPON_1 PPON_2 PPON_3 PPON_4 PPON_5 PPON_6 PPON_7 PPON_8 PPON_9 PPON_10 PPON_11 PPON_12 PPON_13 TEST46 TP_ANALOGIO TP_CHAR_STATUS_REAR TP_CHAR_STATUS_SIDE TP_CLINK_CLK_LAN TP_CLINK_DATA_LAN TP_CLINK_RST_LAN_N TP_DBGDATA_0 TP_DBGDATA_1 TP_DBGDATA_2 TP_DBGDATA_3 TP_DBGDATA_4 TP_DBGDATA_5 TP_DBGDATA_6 TP_DBGDATA_7 TP_DBGDATA_8 TP_DBGDATA_9 TP_DBGDATA_10 TP_DBGDATA_11 TP_DBGDATA_12 TP_DBGDATA_13 TP_DBGDATA_14 TP_DBGDATA_15 TP_DP_AUXN TP_DP_AUXP TP_DP_HPD TP_DP_ML0N TP_DP_ML0P TP_DP_ML1N TP_DP_ML1P TP_DP_ML2N TP_DP_ML2P TP_DP_ML3N TP_DP_ML3P TP_ESPI_ALERT_L TP_GPU_GPIO_0 TP_GPU_GPIO_2 TP_GPU_GPIO_16 TP_LPC_PD TP_NGFF_COEX1 TP_NGFF_COEX2 TP_NGFF_COEX3 TP_NGFF_LED1 TP_NGFF_LED2 TP_NGFF_MLDIR TP_NGFF_PCIE1_RXN TP_NGFF_PCIE1_RXP TP_NGFF_PCIE1_TXN TP_NGFF_PCIE1_TXP TP_NGFF_REFCLKN1 TP_NGFF_REFCLKP1 TP_PLLCHARZ_H TP_PLLCHARZ_L TP_SMB_CLK_MINI TP_SMB_DATA_MINI TP_TEST15 TP_TEST31 TP_TEST40 TP_TEST41 TP_TEST47 TP_TS_A
net group USB_OC: nets CHAR_USBOC4# CHAR_USBOC6# SLP_S3_N USB20_OC_CR1# USB_OC0N USB_OC1N USB_OC2N USB_OC3N USB_OC4N USB_OC5N USB_OC6N USB_OC7N USBVCCTP_OC

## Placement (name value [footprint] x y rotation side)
BT1  BAT-AAA-BAT-034-P06-A-GP-U  [AAA-BAT-034-P06-A-U]  171.04 18.77 0 top
C1  SCD22U10V2KX-2-GP  [C402H22]  135.57 166.28 270 top
C2  SCD22U10V2KX-2-GP  [C402H22]  135.56 165.4 270 top
C3  SCD22U10V2KX-2-GP  [C402H22]  134.17 176.66 0 top
C4  SCD22U10V2KX-2-GP  [C402H22]  133.28 176.66 0 top
C5  SCD22U10V2KX-2-GP  [C402H22]  135.14 176.66 0 top
C6  SCD22U10V2KX-2-GP  [C402H22]  136 176.66 0 top
C7  SCD22U10V2KX-2-GP  [C402H22]  133.66 170.32 270 top
C8  SCD22U10V2KX-2-GP  [C402H22]  133.66 169.46 270 top
C17  SC15P50V2JN-DL-GP  [C402H22]  142.54 169.06 180 top
C18  SC15P50V2JN-DL-GP  [C402H22]  142.54 171.02 0 top
C21  SC150P50V2JN-3DLGP  [C402H22]  136.6 149.45 0 bottom
C22  SC1P50V2CN-3-GP  [C402H22]  141.31 175.53 0 top
C23  SC1P50V2CN-3-GP  [C402H22]  141.32 177.45 180 top
C24  SCD22U10V2KX-2-GP  [C402H22]  164.15 166.44 270 bottom
C25  SCD22U10V2KX-2-GP  [C402H22]  164.15 165.55 270 bottom
C26  SCD22U10V2KX-2-GP  [C402H22]  166.62 177.8 0 bottom
C27  SCD22U10V2KX-2-GP  [C402H22]  157.99 173.74 270 bottom
C28  SCD22U10V2KX-2-GP  [C402H22]  149.99 177.65 90 bottom
C29  SCD22U10V2KX-2-GP  [C402H22]  170.48 173.89 180 bottom
C30  SCD22U10V2KX-2-GP  [C402H22]  170.43 169.88 270 bottom
C31  SCD22U10V2KX-2-GP  [C402H22]  165.4 158.03 180 bottom
C32  SCD22U10V2KX-2-GP  [C402H22]  170.43 177.8 180 bottom
C33  SCD22U10V2KX-2-GP  [C402H22]  168.53 180.85 180 bottom
C34  SCD22U10V2KX-2-GP  [C402H22]  166.54 175.27 180 bottom
C35  SCD22U10V2KX-2-GP  [C402H22]  163.7 160.16 180 bottom
C36  SC180P50V2JN-1DLGP  [C402H22]  154.05 167.39 270 bottom
C37  SC180P50V2JN-1DLGP  [C402H22]  166.75 181.99 0 bottom
C38  SC4D7U6D3V2MX-1-GP  [C402H22]  164.44 175.4 180 bottom
C39  SC4D7U6D3V2MX-1-GP  [C402H22]  163.43 168.14 0 bottom
C40  SC4D7U6D3V2MX-1-GP  [C402H22]  163.7 164.08 180 bottom
C41  SC4D7U6D3V2MX-1-GP  [C402H22]  163.68 162.17 0 bottom
C42  SC4D7U6D3V2MX-1-GP  [C402H22]  162.81 179.45 270 bottom
C43  SC4D7U6D3V2MX-1-GP  [C402H22]  164.56 172.48 0 bottom
C44  SC4D7U6D3V2MX-1-GP  [C402H22]  162.8 181.23 270 bottom
C45  SC4D7U6D3V2MX-1-GP  [C402H22]  165.1 182.63 0 bottom
C46  SC4D7U6D3V2MX-1-GP  [C402H22]  166.62 179.71 180 bottom
C47  SC4D7U6D3V2MX-1-GP  [C402H22]  163.5 158.11 0 bottom
C48  SC4D7U6D3V2MX-1-GP  [C402H22]  155.57 169.93 180 bottom
C49  SC4D7U6D3V2MX-1-GP  [C402H22]  157.24 171.66 90 bottom
C50  SC4D7U6D3V2MX-1-GP  [C402H22]  159.38 179.45 180 bottom
C51  SC4D7U6D3V2MX-1-GP  [C402H22]  152.27 172.85 0 bottom
C52  SC4D7U6D3V2MX-1-GP  [C402H22]  170.48 171.98 180 bottom
C53  SC4D7U6D3V2MX-1-GP  [C402H22]  157.61 170.18 180 bottom
C54  SC4D7U6D3V2MX-1-GP  [C402H22]  162.81 180.34 270 bottom
C55  SC4D7U6D3V2MX-1-GP  [C402H22]  162.56 175.01 0 bottom
C56  SC4D7U6D3V2MX-1-GP  [C402H22]  155.28 181.79 90 bottom
C57  SC4D7U6D3V2MX-1-GP  [C402H22]  155.07 173.35 90 bottom
C58  SCD22U10V2KX-2-GP  [C402H22]  181.29 166.57 90 bottom
C59  SCD22U10V2KX-2-GP  [C402H22]  180.14 163.4 270 bottom
C60  SCD22U10V2KX-2-GP  [C402H22]  183.21 166.57 270 bottom
C61  SCD22U10V2KX-2-GP  [C402H22]  178.21 166.7 270 bottom
C62  SCD22U10V2KX-2-GP  [C402H22]  176.43 173.83 180 bottom
C63  SCD22U10V2KX-2-GP  [C402H22]  189.51 169.42 270 bottom
C64  SCD22U10V2KX-2-GP  [C402H22]  191.9 180.21 270 bottom
C65  SCD22U10V2KX-2-GP  [C402H22]  189.76 172.42 270 bottom
C66  SCD22U10V2KX-2-GP  [C402H22]  178.51 172.21 180 bottom
C67  SCD22U10V2KX-2-GP  [C402H22]  187.96 165.28 270 bottom
C68  SC180P50V2JN-1DLGP  [C402H22]  189.51 170.38 270 bottom
C69  SC180P50V2JN-1DLGP  [C402H22]  190.37 174.88 0 bottom
C70  SC180P50V2JN-1DLGP  [C402H22]  174.52 172.75 0 bottom
C71  SC4D7U6D3V2MX-1-GP  [C402H22]  180.18 169.37 90 bottom
C72  SC4D7U6D3V2MX-1-GP  [C402H22]  178.44 170.21 0 bottom
C73  SC4D7U6D3V2MX-1-GP  [C402H22]  186.82 172.64 90 bottom
C74  SC4D7U6D3V2MX-1-GP  [C402H22]  185.06 173.69 270 bottom
C75  SC4D7U6D3V2MX-1-GP  [C402H22]  188.93 175.31 270 bottom
C76  SC4D7U6D3V2MX-1-GP  [C402H22]  175.96 156.6 90 bottom
C77  SC4D7U6D3V2MX-1-GP  [C402H22]  175.43 158.08 180 bottom
C78  SC4D7U6D3V2MX-1-GP  [C402H22]  191.29 164.64 180 bottom
C79  SC4D7U6D3V2MX-1-GP  [C402H22]  191.9 178.44 270 bottom
C80  SC4D7U6D3V2MX-1-GP  [C402H22]  178.97 158.45 270 bottom
C81  SC4D7U6D3V2MX-1-GP  [C402H22]  189.48 164.67 180 bottom
C82  SC4D7U6D3V2MX-1-GP  [C402H22]  185.42 179.01 180 bottom
C83  SC4D7U6D3V2MX-1-GP  [C402H22]  186.03 165.28 270 bottom
C84  SC4D7U6D3V2MX-1-GP  [C402H22]  191.9 179.32 270 bottom
C85  SC4D7U6D3V2MX-1-GP  [C402H22]  183.69 165.3 270 bottom
C86  SC4D7U6D3V2MX-1-GP  [C402H22]  182.93 169.72 90 bottom
C87  SC4D7U6D3V2MX-1-GP  [C402H22]  180.67 173.86 0 bottom
C88  SC4D7U6D3V2MX-1-GP  [C402H22]  191.88 177.52 270 bottom
C89  SC4D7U6D3V2MX-1-GP  [C402H22]  189.39 166.67 270 bottom
C90  SC4D7U6D3V2MX-1-GP  [C402H22]  178.23 163.35 270 bottom
C91  SC4D7U6D3V2MX-1-GP  [C402H22]  184.98 169.47 180 bottom
C92  SC4D7U6D3V2MX-1-GP  [C402H22]  179.68 166.17 180 bottom
C93  SC4D7U6D3V2MX-1-GP  [C402H22]  186.54 170.31 0 bottom
C94  SC4D7U6D3V2MX-1-GP  [C402H22]  188.77 178.28 270 bottom
C95  SC4D7U6D3V2MX-1-GP  [C402H22]  188.21 180.39 270 bottom
C96  SC4D7U6D3V2MX-1-GP  [C402H22]  190.37 164.67 180 bottom
C97  SC180P50V2JN-1DLGP  [C402H22]  191.27 125.87 270 bottom
C98  SC180P50V2JN-1DLGP  [C402H22]  162.35 131.67 90 bottom
C99  SC180P50V2JN-1DLGP  [C402H22]  162.5 124.23 90 bottom
C100  SC180P50V2JN-1DLGP  [C402H22]  173.71 156.59 90 bottom
C101  SCD22U10V2KX-2-GP  [C402H22]  166.55 151.14 0 bottom
C102  SCD22U10V2KX-2-GP  [C402H22]  162.35 133.45 90 bottom
C103  SCD22U10V2KX-2-GP  [C402H22]  180.05 150.66 270 bottom
C104  SCD22U10V2KX-2-GP  [C402H22]  171.91 154.69 90 bottom
C105  SCD22U10V2KX-2-GP  [C402H22]  184.44 137.83 270 bottom
C106  SCD22U10V2KX-2-GP  [C402H22]  191.27 126.76 270 bottom
C107  SCD22U10V2KX-2-GP  [C402H22]  162.35 132.56 90 bottom
C108  SCD22U10V2KX-2-GP  [C402H22]  170.21 154.38 180 bottom
C109  SCD22U10V2KX-2-GP  [C402H22]  162.35 135.23 90 bottom
C110  SCD22U10V2KX-2-GP  [C402H22]  162.5 122.45 90 bottom
C111  SCD22U10V2KX-2-GP  [C402H22]  162.35 134.34 90 bottom
C112  SCD22U10V2KX-2-GP  [C402H22]  164.06 154.58 90 bottom
C113  SCD22U10V2KX-2-GP  [C402H22]  180.01 149.56 270 bottom
C114  SCD22U10V2KX-2-GP  [C402H22]  184.4 136.91 270 bottom
C115  SC4D7U6D3V2MX-1-GP  [C402H22]  187.32 131.81 270 bottom
C116  SC4D7U6D3V2MX-1-GP  [C402H22]  174.55 153.21 0 bottom
C117  SC4D7U6D3V2MX-1-GP  [C402H22]  161.58 141.25 90 bottom
C118  SC4D7U6D3V2MX-1-GP  [C402H22]  170.96 156.43 90 bottom
C119  SC4D7U6D3V2MX-1-GP  [C402H22]  184.44 138.71 270 bottom
C120  SC4D7U6D3V2MX-1-GP  [C402H22]  187.32 133.59 270 bottom
C121  SC4D7U6D3V2MX-1-GP  [C402H22]  187.32 132.7 270 bottom
C122  SC4D7U6D3V2MX-1-GP  [C402H22]  161.3 147.68 90 bottom
C123  SC4D7U6D3V2MX-1-GP  [C402H22]  161.3 148.57 90 bottom
C124  SC4D7U6D3V2MX-1-GP  [C402H22]  162.5 123.34 90 bottom
C125  SC4D7U6D3V2MX-1-GP  [C402H22]  162.53 126.9 90 bottom
C126  SC4D7U6D3V2MX-1-GP  [C402H22]  179.92 146.46 270 bottom
C127  SC4D7U6D3V2MX-1-GP  [C402H22]  191.27 123.2 270 bottom
C128  SC4D7U6D3V2MX-1-GP  [C402H22]  191.27 124.09 270 bottom
C129  SC4D7U6D3V2MX-1-GP  [C402H22]  191.27 124.98 270 bottom
C130  SC4D7U6D3V2MX-1-GP  [C402H22]  163.55 150.98 0 bottom
C131  SC4D7U6D3V2MX-1-GP  [C402H22]  161.29 145.85 90 bottom
C132  SC4D7U6D3V2MX-1-GP  [C402H22]  161.29 146.74 90 bottom
C133  SC4D7U6D3V2MX-1-GP  [C402H22]  161.58 140.32 90 bottom
C134  SC4D7U6D3V2MX-1-GP  [C402H22]  162.35 130.78 90 bottom
C135  SCD22U10V2KX-2-GP  [C402H22]  159.16 163.85 90 bottom
C136  SCD22U10V2KX-2-GP  [C402H22]  161.39 165.31 270 bottom
C138  SC10U6D3V2MX-2-GP  [C402-TO0D2H28]  158.97 165.91 90 bottom
C139  SCD22U10V2KX-2-GP  [C402H22]  158.91 166.82 90 bottom
C140  SCD22U10V2KX-2-GP  [C402H22]  158.91 167.69 90 bottom
C141  SC1U10V2KX-1DLGP  [C402H22]  160.25 169.88 0 bottom
C142  SCD22U10V2KX-2-GP  [C402H22]  157.02 168.79 90 bottom
C143  SC22U6D3V3MX-1-DL-GP  [C603H40]  139.5 162.36 90 bottom
C144  SCD22U10V2KX-2-GP  [C402H22]  159.16 162.97 90 bottom
C145  SCD22U10V2KX-2-GP  [C402H22]  159.77 159.41 90 bottom
C147  SC22U6D3V3MX-1-DL-GP  [C603H40]  179.55 102.79 90 bottom
C148  SC22U6D3V5MX-2-LL-GP  [C805H54]  170.71 115.91 180 bottom
C149  SC22U6D3V5MX-2-LL-GP  [C805H54]  199.24 116.69 180 bottom
C150  SC22U6D3V3MX-1-DL-GP  [C603H40]  175.49 102.54 270 bottom
C151  SCD1U25V2KX-1-DL-GP  [C402H22]  189.87 129.77 90 top
C152  SC1U10V2KX-1DLGP  [C402H22]  165.01 106.94 0 bottom
C153  SC1U10V2KX-1DLGP  [C402H22]  194.45 107.11 0 bottom
C154  SC1U10V2KX-1DLGP  [C402H22]  196.36 113.84 180 bottom
C155  SC1U10V2KX-1DLGP  [C402H22]  159.87 106.7 0 bottom
C156  SCD1U25V2KX-1-DL-GP  [C402H22]  209.74 115.11 180 bottom
C157  SCD1U25V2KX-1-DL-GP  [C402H22]  157.81 91.26 90 bottom
C158  SCD1U25V2KX-1-DL-GP  [C402H22]  202.97 106.5 0 bottom
C159  SCD1U25V2KX-1-DL-GP  [C402H22]  205.73 99.05 180 bottom
C160  SCD1U25V2KX-1-DL-GP  [C402H22]  152.25 116.03 90 bottom
C161  SCD1U25V2KX-1-DL-GP  [C402H22]  149.43 117.53 0 bottom
C162  SC2D2U10V3KX-1DLGP-U  [C603H36]  148.29 117.91 0 bottom
C163  SC10U6D3V3MX-DL-GP  [C603H36]  154.93 106.86 0 bottom
C164  SCD1U25V2KX-1-DL-GP  [C402H22]  176.78 104.78 180 bottom
C165  SC1KP50V2KX-1DLGP  [C402H22]  175.77 104.78 180 bottom
C166  SCD1U25V2KX-1-DL-GP  [C402H22]  146.08 103.96 180 bottom
C167  SC4D7U6D3V3KX-DLGP  [C603H36]  144.98 103.73 180 bottom
C168  SCD1U25V2KX-1-DL-GP  [C402H22]  148.51 115.9 90 bottom
C169  SCD1U25V2KX-1-DL-GP  [C402H22]  148.51 114.96 90 bottom
C170  SC8P50V2DN-1DL-GP  [C402H22]  202.06 106.48 0 bottom
C171  SC2200P50V2KX-2DLGP  [C402H22]  171.19 108.63 0 bottom
C172  SC22U6D3V3MX-1-DL-GP  [C603H40]  190.88 90.3 90 bottom
C173  SC22U6D3V5MX-2-LL-GP  [C805H54]  187.73 106.96 270 bottom
C174  SC22U6D3V3MX-1-DL-GP  [C603H40]  192.31 98.7 270 bottom
C175  SC22U6D3V3MX-1-DL-GP  [C603H40]  173.78 90.36 90 bottom
C176  SC22U6D3V5MX-2-LL-GP  [C805H54]  187.76 104.93 270 bottom
C177  SC1U10V2KX-1DLGP  [C402H22]  214.37 107.91 0 bottom
C178  SC1U10V2KX-1DLGP  [C402H22]  187.95 99.96 0 bottom
C179  SC1U10V2KX-1DLGP  [C402H22]  157.32 99.66 180 bottom
C180  SC1U10V2KX-1DLGP  [C402H22]  152.13 97.96 90 bottom
C181  SCD1U25V2KX-1-DL-GP  [C402H22]  158 114.93 180 bottom
C182  SCD1U25V2KX-1-DL-GP  [C402H22]  202.71 92.56 0 bottom
C183  SCD1U25V2KX-1-DL-GP  [C402H22]  193.29 90.65 180 bottom
C184  SCD1U25V2KX-1-DL-GP  [C402H22]  197.19 99.07 180 bottom
C185  SCD1U25V2KX-1-DL-GP  [C402H22]  167.1 91.06 90 bottom
C186  SC10U6D3V3MX-GP  [C603H38]  160.12 91.26 270 bottom
C187  SCD1U25V2KX-1-DL-GP  [C402H22]  173.99 86.23 0 top
C188  SC1KP50V2KX-1DLGP  [C402H22]  174.88 86.23 0 top
C189  SCD1U25V2KX-1-DL-GP  [C402H22]  147.93 101.09 90 bottom
C190  SCD1U25V2KX-1-DL-GP  [C402H22]  147.93 102.01 90 bottom
C191  SC2D2U10V3KX-1DLGP-U  [C603H36]  151.15 102.07 270 bottom
C192  SCD1U25V2KX-1-DL-GP  [C402H22]  150.89 100.95 270 bottom
C193  SC4D7U6D3V3KX-DLGP  [C603H36]  150.72 91.26 180 bottom
C194  SCD1U25V2KX-1-DL-GP  [C402H22]  149.94 93.31 270 bottom
C195  SCD22U10V2KX-2-GP  [C402H22]  145.26 54.74 180 top
C196  SCD22U10V2KX-2-GP  [C402H22]  146.18 54.74 180 top
C197  SCD22U10V2KX-2-GP  [C402H22]  139.45 53.82 270 top
C198  SCD22U10V2KX-2-GP  [C402H22]  139.45 54.71 270 top
C199  SCD22U10V2KX-2-GP  [C402H22]  142.24 50.09 270 top
C200  SCD22U10V2KX-2-GP  [C402H22]  142.24 50.98 270 top
C201  SCD22U10V2KX-2-GP  [C402H22]  142.24 48.13 270 top
C202  SCD22U10V2KX-2-GP  [C402H22]  142.24 49.02 270 top
C203  SCD1U25V2KX-1-DL-GP  [C402H22]  175.83 43.1 90 top
C204  SCD1U25V2KX-1-DL-GP  [C402H22]  175.83 43.96 90 top
C205  SCD1U25V2KX-1-DL-GP  [C402H22]  173.23 43 90 bottom
C206  SCD1U25V2KX-1-DL-GP  [C402H22]  173.23 42.11 90 bottom
C207  SC100P50V2JN-3DLGP  [C402H22]  160.1 32.61 180 bottom
C208  SC1U10V2KX-1DLGP  [C402H22]  174.12 53.34 180 top
C209  SC15P50V2JN-DL-GP  [C402H22]  170.31 29.34 0 top
C210  SC15P50V2JN-DL-GP  [C402H22]  170.31 31.37 180 top
C211  SC22U6D3V5MX-2DLGP  [C805H54]  159.77 52.53 270 bottom
C212  SCD1U25V2KX-1-DL-GP  [C402H22]  159 51.05 270 bottom
C213  SC22U6D3V5MX-2DLGP  [C805H54]  146.28 51.05 180 bottom
C214  SC22U6D3V5MX-2DLGP  [C805H54]  148.26 51.05 180 bottom
C215  SC22U6D3V5MX-2DLGP  [C805H54]  140.41 64.11 90 bottom
C216  SC22U6D3V5MX-2DLGP  [C805H54]  146.86 62.94 180 top
C217  SC22U6D3V5MX-2DLGP  [C805H54]  144.32 46.89 0 bottom
C218  SC22U6D3V5MX-2DLGP  [C805H54]  135.1 47.78 180 top
C219  SC22U6D3V5MX-2DLGP  [C805H54]  135.13 43.81 0 top
C220  SC22U6D3V5MX-2DLGP  [C805H54]  138.99 47.78 180 top
C221  SC22U6D3V5MX-2DLGP  [C805H54]  137.06 47.78 180 top
C222  SC22U6D3V5MX-2DLGP  [C805H54]  146.33 46.89 0 bottom
C223  SCD1U25V2KX-1-DL-GP  [C402H22]  164.08 40.26 90 bottom
C224  SCD1U25V2KX-1-DL-GP  [C402H22]  164.08 39.37 90 bottom
C225  SCD1U25V2KX-1-DL-GP  [C402H22]  153.8 51.05 180 bottom
C226  SCD1U25V2KX-1-DL-GP  [C402H22]  166.24 46.61 270 bottom
C227  SCD1U25V2KX-1-DL-GP  [C402H22]  166.24 44.96 270 bottom
C228  SCD1U25V2KX-1-DL-GP  [C402H22]  166.24 43.43 270 bottom
C229  SC1U10V2KX-1DLGP  [C402H22]  166.24 42.55 270 bottom
C230  SC1U10V2KX-1DLGP  [C402H22]  161.85 50.19 0 bottom
C231  SC1U10V2KX-1DLGP  [C402H22]  155.83 48.39 90 bottom
C232  SC1U10V2KX-1DLGP  [C402H22]  160.27 47.75 180 bottom
C233  SC1U10V2KX-1DLGP  [C402H22]  162.94 43.43 90 bottom
C234  SC1U10V2KX-1DLGP  [C402H22]  162.94 44.96 90 bottom
C235  SC1U10V2KX-1DLGP  [C402H22]  155.83 47.37 90 bottom
C236  SC1U10V2KX-1DLGP  [C402H22]  159.49 39.75 180 bottom
C237  SC1U10V2KX-1DLGP  [C402H22]  160.91 42.42 0 bottom
C238  SC1U10V2KX-1DLGP  [C402H22]  162.69 39.75 180 bottom
C239  SC22U6D3V5MX-2DLGP  [C805H54]  155.7 32.26 90 bottom
C240  SCD1U25V2KX-1-DL-GP  [C402H22]  155.68 33.76 90 bottom
C241  SCD1U25V2KX-1-DL-GP  [C402H22]  155.32 45.97 0 bottom
C242  SCD1U25V2KX-1-DL-GP  [C402H22]  152.15 51.05 180 bottom
C243  SCD1U25V2KX-1-DL-GP  [C402H22]  149.73 51.56 180 bottom
C244  SCD1U25V2KX-1-DL-GP  [C402H22]  160.38 39.75 180 bottom
C245  SCD1U25V2KX-1-DL-GP  [C402H22]  161.8 48.01 180 bottom
C246  SCD1U25V2KX-1-DL-GP  [C402H22]  158.65 48.77 0 bottom
C247  SC1U10V2KX-1DLGP  [C402H22]  165.48 48.26 270 bottom
C248  SC1U10V2KX-1DLGP  [C402H22]  163.45 50.42 0 bottom
C249  SC1U10V2KX-1DLGP  [C402H22]  163.07 46.61 90 bottom
C250  SC1U10V2KX-1DLGP  [C402H22]  153.77 41.43 180 bottom
C251  SC1U10V2KX-1DLGP  [C402H22]  151.46 41.38 180 bottom
C252  SC1U10V2KX-1DLGP  [C402H22]  150.6 41.38 180 bottom
C253  SC1U10V2KX-1DLGP  [C402H22]  149.73 41.38 180 bottom
C254  SC1U10V2KX-1DLGP  [C402H22]  148.08 45.47 0 bottom
C255  SC1U10V2KX-1DLGP  [C402H22]  149.48 45.47 0 bottom
C256  SC1U10V2KX-1DLGP  [C402H22]  153.77 43.87 0 bottom
C257  SC1U10V2KX-1DLGP  [C402H22]  152.15 43.81 0 bottom
C258  SC1U10V2KX-1DLGP  [C402H22]  157.48 44.96 270 bottom
C259  SC1U10V2KX-1DLGP  [C402H22]  157.48 43.43 270 bottom
C260  SC1U10V2KX-1DLGP  [C402H22]  158.32 47.37 270 bottom
C261  SC1U10V2KX-1DLGP  [C402H22]  158.6 39.75 180 bottom
C262  SC22U6D3V5MX-2DLGP  [C805H54]  146.69 36.27 90 top
C263  SCD1U25V2KX-1-DL-GP  [C402H22]  156.41 40.64 180 bottom
C264  SCD1U25V2KX-1-DL-GP  [C402H22]  161.8 38.99 180 bottom
C275  SC1U6D3V2KX-GP  [C402H22]  117.93 57.15 270 bottom
C276  SCD1U25V2KX-1-DL-GP  [C402H22]  114.86 63.9 270 top
C277  SC2D2U10V3KX-1GP  [C603H36]  114.42 64.99 270 top
C278  SCD1U25V2KX-1-DL-GP  [C402H22]  102.56 52.11 270 bottom
C279  SCD1U25V2KX-1-DL-GP  [C402H22]  108.97 60.35 90 bottom
C280  SCD1U25V2KX-1-DL-GP  [C402H22]  108.75 41.71 0 top
C281  SCD1U25V2KX-1-DL-GP  [C402H22]  119.15 52.15 0 bottom
C282  SCD1U25V2KX-1-DL-GP  [C402H22]  118.27 52.14 0 bottom
C283  SC2D2U10V3KX-1DLGP-U  [C603H36]  97.16 55.12 270 top
C284  SCD1U25V2KX-1-DL-GP  [C402H22]  102.41 78.11 0 top
C291  SCD1U25V2KX-1-DL-GP  [C402H22]  116.48 46.76 180 bottom
C292  SC10U6D3V3MX-DL-GP  [C603H36]  115.44 46.38 180 bottom
C294  SC470P50V2KX-3DLGP  [C402H22]  98.91 49.22 270 bottom
C295  SC2200P50V2KX-2DLGP  [C402H22]  98.91 48.23 270 bottom
C297  SC1U10V2KX-1DLGP  [C402H22]  132.05 87.15 0 top
C298  SC1U10V2KX-1DLGP  [C402H22]  128.02 42.21 0 top
C299  SC1U10V2KX-1DLGP  [C402H22]  129.98 42.55 0 top
C300  SC1U10V2KX-1DLGP  [C402H22]  126.42 44.63 90 top
C301  SC10U25V5KX-DL-GP  [C805H58]  14.61 178.56 180 top
C309  SC2D2U10V3KX-1DLGP-U  [C603H36]  206.58 49.81 0 top
C310  SCD1U50V3KX-DL-GP  [C603H35]  208.95 37.8 180 bottom
C311  SC2D2U10V3KX-1DLGP-U  [C603H36]  210.13 37.8 180 bottom
C312  SC2D2U10V3KX-1DLGP-U  [C603H36]  195.1 46.41 270 top
C313  SCD1U50V3KX-DL-GP  [C603H35]  194.82 45.21 270 top
C314  SC10U6D3V3MX-DL-GP  [C603H36]  197.95 49.98 0 top
C315  SC2D2U10V3KX-1DLGP-U  [C603H36]  208.56 48.13 270 top
C316  SCD1U50V3KX-DL-GP  [C603H35]  209.33 44.93 270 bottom
C317  SC10U6D3V3MX-DL-GP  [C603H36]  209.33 43.63 270 bottom
C318  SC10U25V5KX-DL-GP  [C805H58]  194.41 44.66 90 bottom
C319  SCD1U50V3KX-DL-GP  [C603H35]  194.73 46.33 90 bottom
C320  SC2D2U10V3KX-1DLGP-U  [C603H36]  209.93 46.63 90 top
C321  SCD1U25V2KX-1-DL-GP  [C402H22]  207.01 45.09 90 bottom
C322  SC10U6D3V3MX-DL-GP  [C603H36]  194.26 44.04 270 top
C323  SC2D2U10V3KX-1DLGP-U  [C603H36]  209.88 44.6 90 top
C324  SCD1U50V3KX-DL-GP  [C603H35]  202.84 38.48 0 bottom
C325  SC2D2U10V3KX-1DLGP-U  [C603H36]  200.76 38.46 0 bottom
C326  SC100P50V2JN-3DLGP  [C402H22]  204.34 43.05 90 bottom
C327  SC1U10V2KX-1DLGP  [C402H22]  194.74 40.92 180 bottom
C328  SCD1U50V3KX-DL-GP  [C603H35]  198.37 43.05 270 bottom
C329  SCD1U50V3KX-DL-GP  [C603H35]  209.36 41.04 270 bottom
C330  SCD1U50V3KX-DL-GP  [C603H35]  212.01 43.15 0 top
C331  SC10U6D3V3MX-DL-GP  [C603H36]  209.85 42.98 90 top
C332  SC4D7U6D3V3KX-DLGP  [C603H36]  209.36 42.24 270 bottom
C333  SCD1U50V3KX-DL-GP  [C603H35]  198.35 41.86 270 bottom
C334  SCD1U50V3KX-DL-GP  [C603H35]  204.84 39.04 90 bottom
C335  SC4D7U6D3V3KX-DLGP  [C603H36]  204.84 40.21 90 bottom
C336  SC10U25V5KX-DL-GP  [C805H58]  194.41 47.9 90 bottom
C337  SC33P50V2JN-3DLGP  [C402H22]  194.18 41.66 270 top
C338  SC22P50V2JN-4DLGP  [C402H22]  210.27 34.55 90 top
C340  SC100P50V2JN-3DLGP  [C402H22]  202.03 53.34 0 bottom
C341  SC100P50V2JN-3DLGP  [C402H22]  200.79 53.34 0 bottom
C342  SC100P50V2JN-3DLGP  [C402H22]  203.23 54.94 180 top
C343  SC100P50V2JN-3DLGP  [C402H22]  207.34 52.27 0 top
C344  SCD1U50V3KX-DL-GP  [C603H35]  208.25 34.82 0 top
C345  SCD1U25V2KX-1-DL-GP  [C402H22]  223.42 74.17 90 top
C347  SC22P50V2JN-4DLGP  [C402H22]  215.81 25.18 90 bottom
C348  SC22P50V2JN-4DLGP  [C402H22]  215.81 26.04 90 bottom
C349  SC22P50V2JN-4DLGP  [C402H22]  219.33 28.96 90 top
C350  SC22P50V2JN-4DLGP  [C402H22]  200.87 33.54 0 top
C351  SC27P50V3JN-DLGP  [C603H35]  218.31 40.89 180 bottom
C352  SC27P50V3JN-DLGP  [C603H35]  221.74 40.01 90 bottom
C353  SC680P-DLGP  [C603H36]  217.17 13.44 180 bottom
C354  SC680P-DLGP  [C603H36]  211.99 12.7 90 bottom
C355  SC680P-DLGP  [C603H36]  211.96 11.81 180 top
C356  SC680P-DLGP  [C603H36]  206.02 13.03 180 top
C357  SC330P50V3JN-DL-GP  [C603H36]  206.81 17.71 270 top
C358  SC330P50V3JN-DL-GP  [C603H36]  217.17 16.38 0 bottom
C359  SC330P50V3JN-DL-GP  [C603H36]  210.72 15.85 90 bottom
C360  SC330P50V3JN-DL-GP  [C603H36]  211.25 16.51 270 top
C361  SCD22U50V3KX-1-GP  [C603H38]  218.31 18.31 90 bottom
C362  SCD22U50V3KX-1-GP  [C603H38]  210.72 17.04 90 bottom
C363  SCD22U50V3KX-1-GP  [C603H38]  211.23 17.7 270 top
C364  SCD22U50V3KX-1-GP  [C603H38]  206.81 18.93 270 top
C365  SCD1U50V3KX-DL-GP  [C603H35]  215.42 21.59 180 bottom
C366  SC1KP50V2KX-1DLGP  [C402H22]  218.9 21.31 90 top
C367  SC1KP50V2KX-1DLGP  [C402H22]  218.9 20.42 270 top
C368  SCD1U25V2KX-1-DL-GP  [C402H22]  212.55 21.29 180 bottom
C369  SC22U25V5MX-5-GP  [C805H58]  214.69 15.78 0 top
C370  SCD1U25V2KX-1-DL-GP  [C402H22]  208.81 21.26 180 bottom
C371  SC1KP50V2KX-1DLGP  [C402H22]  209.75 21.28 0 bottom
C372  SCD1U25V2KX-1-DL-GP  [C402H22]  206.35 20.14 270 top
C373  SC22U25V5MX-5-GP  [C805H58]  217.33 15.78 0 top
C374  SC1U50V3KX-1-GP  [C603H36]  220.98 23.09 270 top
C375  SC1KP50V2KX-1DLGP  [C402H22]  211.58 21.28 0 bottom
C376  SC1U50V3KX-1-GP  [C603H36]  205.41 21.8 270 top
C377  SCD1U25V2KX-1-DL-GP  [C402H22]  206.07 22.84 270 top
C378  SC4D7U25V5KX-DL-GP  [C805H54]  208.64 24.59 270 bottom
C379  SC2D2U10V3KX-1DLGP-U  [C603H36]  212.78 31.52 180 top
C380  SCD1U25V2KX-1-DL-GP  [C402H22]  211.4 33.66 90 top
C381  SC1U50V3KX-1-GP  [C603H36]  216.77 31.24 180 top
C382  SCD1U25V2KX-1-DL-GP  [C402H22]  215.72 31.44 180 top
C383  SC1U50V3KX-1-GP  [C603H36]  213.61 27.81 180 bottom
C384  SCD1U25V2KX-1-DL-GP  [C402H22]  214.73 27.61 180 bottom
C385  SCD1U25V2KX-1-DL-GP  [C402H22]  210.46 31.16 0 bottom
C386  SC1U50V3KX-1-GP  [C603H36]  211.58 31.39 0 bottom
C387  SC680P-DLGP  [C603H36]  202.13 15.27 90 bottom
C388  SC680P-DLGP  [C603H36]  194.23 13.18 90 bottom
C389  SC680P-DLGP  [C603H36]  196.85 13.08 270 top
C390  SC680P-DLGP  [C603H36]  190.42 12.24 270 top
C391  SC330P50V3JN-DL-GP  [C603H36]  190.05 18.54 270 top
C392  SC330P50V3JN-DL-GP  [C603H36]  200.7 18.21 90 bottom
C393  SC330P50V3JN-DL-GP  [C603H36]  195.56 17.55 90 bottom
C394  SC330P50V3JN-DL-GP  [C603H36]  194.73 17.73 270 top
C395  SCD22U50V3KX-1-GP  [C603H38]  200.7 19.43 90 bottom
C396  SCD22U50V3KX-1-GP  [C603H38]  195.55 18.75 90 bottom
C397  SCD22U50V3KX-1-GP  [C603H38]  194.69 18.95 270 top
C398  SCD22U50V3KX-1-GP  [C603H38]  190.05 19.76 270 top
C399  SCD1U50V3KX-DL-GP  [C603H35]  198.4 23.28 180 bottom
C400  SC1KP50V2KX-1DLGP  [C402H22]  195.37 22.75 0 bottom
C401  SC1KP50V2KX-1DLGP  [C402H22]  202.92 20.22 270 top
C402  SCD1U25V2KX-1-DL-GP  [C402H22]  194.41 22.74 180 bottom
C403  SC22U25V5MX-5-GP  [C805H58]  198.13 17.18 0 top
C404  SCD1U25V2KX-1-DL-GP  [C402H22]  191.69 23.26 0 bottom
C405  SC1KP50V2KX-1DLGP  [C402H22]  202.92 21.13 90 top
C406  SC1KP50V2KX-1DLGP  [C402H22]  192.66 22.75 0 bottom
C407  SCD1U25V2KX-1-DL-GP  [C402H22]  193.52 22.75 0 bottom
C408  SC22U25V5MX-5-GP  [C805H58]  201.41 16.55 0 top
C409  SC1U50V3KX-1-GP  [C603H36]  203.4 22.96 180 top
C410  SC1U50V3KX-1-GP  [C603H36]  188.33 21.64 270 top
C411  SCD1U25V2KX-1-DL-GP  [C402H22]  188.49 22.68 270 top
C412  SC4D7U25V5KX-DL-GP  [C805H54]  191.06 25.76 270 bottom
C413  SC2D2U10V3KX-1DLGP-U  [C603H36]  195.91 32.11 180 top
C414  SCD1U25V2KX-1-DL-GP  [C402H22]  194.05 33.7 90 top
C415  SC1U50V3KX-1-GP  [C603H36]  200.86 32.94 270 bottom
C416  SCD1U25V2KX-1-DL-GP  [C402H22]  200.56 31.42 270 bottom
C417  SC1U50V3KX-1-GP  [C603H36]  199.47 28.14 180 bottom
C418  SCD1U25V2KX-1-DL-GP  [C402H22]  199.52 31.19 90 top
C419  SCD1U25V2KX-1-DL-GP  [C402H22]  194.72 29.77 90 bottom
C420  SC1U50V3KX-1-GP  [C603H36]  194.72 28.73 90 bottom
C423  SCD1U25V2KX-1-DL-GP  [C402H22]  220.29 20.42 180 top
C424  SCD1U25V2KX-1-DL-GP  [C402H22]  179.5 11.15 270 bottom
C425  SCD1U25V2KX-1-DL-GP  [C402H22]  103.2 39.78 90 top
C426  SC1KP50V2KX-1DLGP  [C402H22]  173.46 11.73 180 bottom
C427  SCD1U25V2KX-1-DL-GP  [C402H22]  178.03 10.06 270 top
C428  SC1KP50V2KX-1DLGP  [C402H22]  179.68 5.11 0 top
C434  SC10U25V5KX-DL-GP  [C805H58]  225.58 64.69 0 top
C435  SCD1U25V2KX-1-DL-GP  [C402H22]  222.02 64.82 0 top
